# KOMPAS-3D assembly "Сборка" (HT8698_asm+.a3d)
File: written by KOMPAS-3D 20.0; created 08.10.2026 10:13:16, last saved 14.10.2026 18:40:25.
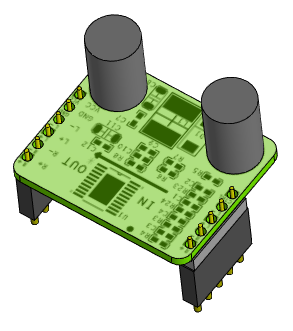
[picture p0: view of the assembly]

Document properties: Полное имя файла: D:\myProjects\Progect_esp32\box_compas\усилитель\HT8698_asm+.a3d

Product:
- Part/product: Сборка
    Масса: 0.0226054
  - Component [detail]: Деталь  | Масса: 0.00190694; source file: ..\разъемы\pbs_6.m3d
  - Component [detail]: Деталь  | Масса: 0.00157243; source file: ..\разъемы\pbs_5.m3d
  - Component [detail]: Деталь  | Масса: 0.0176922; source file: HT8698.m3d
  - Component [detail]: Деталь  | Масса: 0.00078211; source file: ..\разъемы\pls_6.m3d
  - Component [detail]: Деталь  | Масса: 0.000651758; source file: ..\разъемы\pls_5.m3d

Referenced files in D:\myProjects\Progect_esp32\box_compas\усилитель\: HT8698.m3d
Referenced files in D:\myProjects\Progect_esp32\box_compas\разъемы\: pls_6.m3d, pls_5.m3d, pbs_5.m3d, pbs_6.m3d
